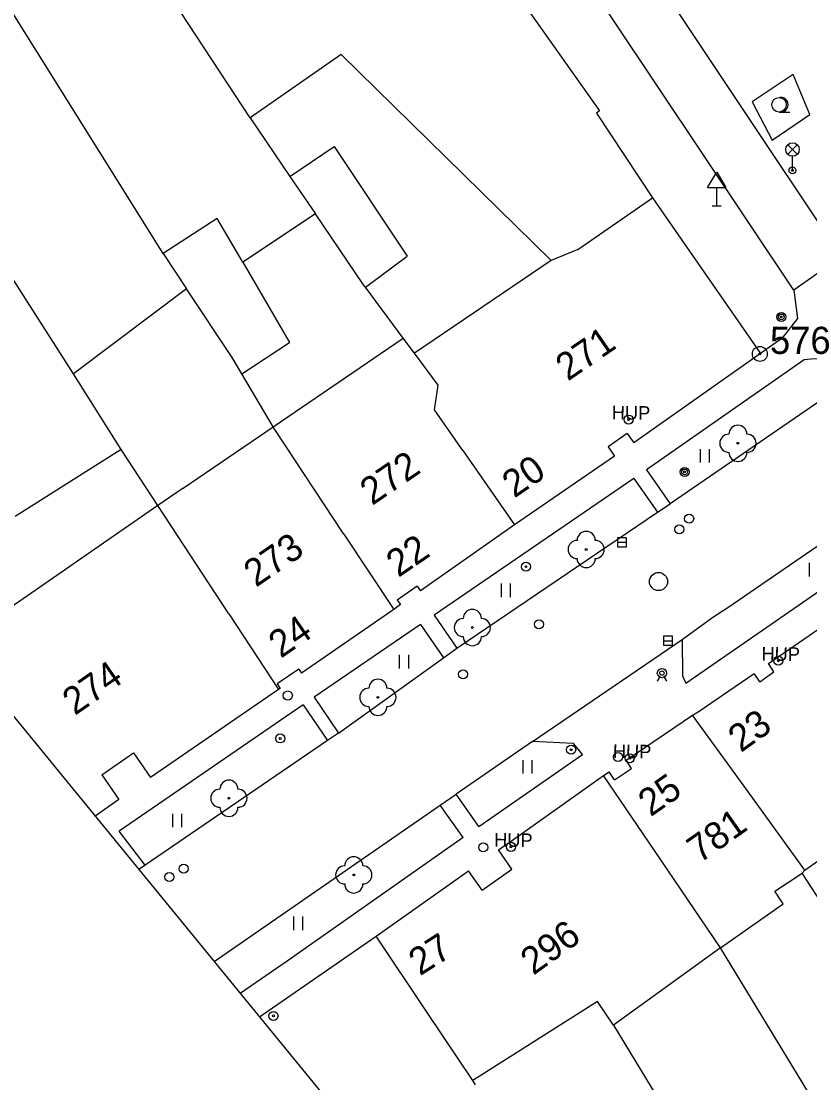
# Model space of a CAD drawing. Extents: x -492431 to -49218, y -1127123 to -112687.
# Drawn here: x -492383.5 to -492340, y -1127091 to -1127032.4 of the extents above; entities that cross this region are included whole.
import ezdxf

# ---------------------------------------------------------------- set-up
doc = ezdxf.new("R2010")
doc.units = 0
for name, color, linetype in [('Vrstva 1', 7, 'Continuous'), ('Vrstva 10', 7, 'Continuous'), ('Vrstva 11', 7, 'Continuous'), ('Vrstva 21', 7, 'Continuous'), ('Vrstva 22', 7, 'Continuous'), ('Vrstva 25', 7, 'Continuous'), ('Vrstva 27', 7, 'Continuous'), ('Vrstva 28', 7, 'Continuous'), ('Vrstva 31', 7, 'Continuous'), ('Vrstva 33', 7, 'Continuous'), ('Vrstva 34', 7, 'Continuous'), ('Vrstva 36', 7, 'Continuous'), ('Vrstva 42', 7, 'Continuous'), ('Vrstva 43', 7, 'Continuous'), ('Vrstva 44', 7, 'Continuous'), ('Vrstva 5', 7, 'Continuous'), ('Vrstva 60', 7, 'Continuous'), ('Vrstva 63', 7, 'Continuous'), ('Vrstva 7', 7, 'Continuous')]:
    doc.layers.add(name, color=color, linetype=linetype)

msp = doc.modelspace()

# ---------------------------------------------------------------- linework, layer by layer
at = {"layer": 'Vrstva 1'}
msp.add_lwpolyline([(-492431.031, -1126895.427), (-492431.031, -1127013.124), (-492341.24, -1127122.91)], dxfattribs=at)
at = {"layer": 'Vrstva 10'}
for p, q in [((-492340.27, -1127051.1), (-492348.97, -1127057.18)), ((-492337.07, -1127051.78), (-492347.66, -1127059.05)), ((-492348.97, -1127057.18), (-492347.66, -1127059.05)), ((-492349.66, -1127057.66), (-492360.68, -1127065.2)), ((-492349.66, -1127057.66), (-492348.36, -1127059.52)), ((-492346.79, -1127068.94), (-492335.59, -1127061.2)), ((-492345.31, -1127065.3), (-492344.47, -1127064.77)), ((-492361.43, -1127065.72), (-492367.3, -1127069.73)), ((-492361.43, -1127065.72), (-492360.17, -1127067.55)), ((-492360.68, -1127065.2), (-492359.43, -1127067.02)), ((-492347, -1127066.53), (-492345.31, -1127065.3)), ((-492355.26, -1127072.16), (-492347, -1127066.53)), ((-492347, -1127066.53), (-492346.97, -1127068.55)), ((-492346.97, -1127068.55), (-492346.79, -1127068.94)), ((-492367.3, -1127069.73), (-492365.95, -1127071.7)), ((-492367.91, -1127070.15), (-492378.05, -1127077.12)), ((-492367.91, -1127070.15), (-492366.56, -1127072.12)), ((-492355.26, -1127072.16), (-492359.47, -1127075.08)), ((-492352.99, -1127072.27), (-492355.26, -1127072.16)), ((-492352.49, -1127072.89), (-492352.99, -1127072.27)), ((-492358.22, -1127076.86), (-492352.49, -1127072.89)), ((-492358.22, -1127076.86), (-492359.47, -1127075.08)), ((-492359.08, -1127077.47), (-492360.34, -1127075.68)), ((-492376.61, -1127078.99), (-492378.05, -1127077.12)), ((-492359.08, -1127077.47), (-492368.79, -1127084.29)), ((-492376.61, -1127078.99), (-492376.962, -1127079.233)), ((-492368.79, -1127084.29), (-492371.373, -1127086.066))]:
    msp.add_line(p, q, dxfattribs=at)
for points in [[(-492368.22, -1127000.44), (-492338.22, -1127045.43)], [(-492340.83, -1127047.27), (-492370.84, -1127002.32)], [(-492338.22, -1127045.43), (-492340.83, -1127047.27)], [(-492340.83, -1127047.27), (-492340.63, -1127048.82), (-492341.49, -1127049.93), (-492342.67, -1127050.76)], [(-492338.96, -1127051.13), (-492339.69, -1127051.05), (-492340.27, -1127051.1)], [(-492359.43, -1127067.02), (-492348.36, -1127059.52), (-492347.66, -1127059.05)], [(-492344.47, -1127064.77), (-492336.73, -1127059.46)], [(-492365.95, -1127071.7), (-492360.17, -1127067.55), (-492359.43, -1127067.02)], [(-492365.95, -1127071.7), (-492366.56, -1127072.12), (-492376.61, -1127078.99)], [(-492360.34, -1127075.68), (-492359.47, -1127075.08)], [(-492372.806, -1127084.315), (-492360.34, -1127075.68)]]:
    msp.add_lwpolyline(points, dxfattribs=at)
at = {"layer": 'Vrstva 11'}
for points in [[(-492370.82, -1127037.75), (-492383.12, -1127019)], [(-492375.63, -1127045.24), (-492389.76, -1127022.63)], [(-492365.81, -1127034.25), (-492370.82, -1127037.75)], [(-492354.23, -1127045.63), (-492365.81, -1127034.25)], [(-492370.82, -1127037.75), (-492368.63, -1127040.99)], [(-492368.63, -1127040.99), (-492366.2, -1127039.34)], [(-492366.2, -1127039.34), (-492362.17, -1127045.38)], [(-492368.63, -1127040.99), (-492367.23, -1127043.05)], [(-492372.65, -1127043.31), (-492375.63, -1127045.24)], [(-492371.24, -1127045.71), (-492372.65, -1127043.31)], [(-492367.23, -1127043.05), (-492371.24, -1127045.71)], [(-492364.57, -1127046.97), (-492367.23, -1127043.05)], [(-492380.58, -1127051.87), (-492385.37, -1127044.39)], [(-492352.75, -1127045.01), (-492354.23, -1127045.63)], [(-492375.63, -1127045.24), (-492374.34, -1127047.18)], [(-492371.24, -1127045.71), (-492368.65, -1127050.14)], [(-492364.47, -1127047.1), (-492362.17, -1127045.38)], [(-492354.23, -1127045.63), (-492361.77, -1127050.73)], [(-492364.47, -1127047.1), (-492364.57, -1127046.97)], [(-492374.34, -1127047.18), (-492380.58, -1127051.87)], [(-492371.82, -1127050.98), (-492374.34, -1127047.18)], [(-492362.38, -1127049.91), (-492364.47, -1127047.1)], [(-492369.55, -1127054.8), (-492362.38, -1127049.91)], [(-492361.77, -1127050.73), (-492362.38, -1127049.91)], [(-492371.28, -1127051.88), (-492368.65, -1127050.14)], [(-492371.28, -1127051.88), (-492371.82, -1127050.98)], [(-492360.45, -1127052.51), (-492361.77, -1127050.73)], [(-492377.94, -1127056.05), (-492380.58, -1127051.87)], [(-492369.55, -1127054.8), (-492371.28, -1127051.88)], [(-492360.65, -1127053.87), (-492360.45, -1127052.51)], [(-492359.09, -1127056.1), (-492360.65, -1127053.87)], [(-492374.52, -1127058.18), (-492369.55, -1127054.8)], [(-492369.47, -1127054.95), (-492369.55, -1127054.8)], [(-492365.66, -1127060.72), (-492369.47, -1127054.95)], [(-492377.94, -1127056.05), (-492383.79, -1127059.75)], [(-492375.92, -1127059.15), (-492377.94, -1127056.05)], [(-492374.52, -1127058.18), (-492375.92, -1127059.15)], [(-492375.92, -1127059.15), (-492387.075, -1127066.868)], [(-492372, -1127065.12), (-492375.92, -1127059.15)], [(-492340.22, -1127079.27), (-492343.49, -1127074.77)], [(-492340.22, -1127079.27), (-492337.7, -1127077.46)], [(-492344.88, -1127083.55), (-492348.52, -1127078.19)], [(-492341.89, -1127080.42), (-492340.38, -1127079.43)], [(-492340.38, -1127079.43), (-492340.22, -1127079.27)], [(-492338.31, -1127082.6), (-492340.38, -1127079.43)], [(-492341.43, -1127081.13), (-492341.89, -1127080.42)], [(-492344.88, -1127083.55), (-492341.43, -1127081.13)], [(-492344.88, -1127083.55), (-492350.79, -1127087.82)], [(-492337.52, -1127095.66), (-492344.88, -1127083.55)], [(-492350.79, -1127087.82), (-492351.67, -1127086.51), (-492358.54, -1127090.88)], [(-492358.54, -1127090.88), (-492361.09, -1127087.07)], [(-492350.79, -1127087.82), (-492343.24, -1127100.24)], [(-492358.4, -1127091.12), (-492358.54, -1127090.88)]]:
    msp.add_lwpolyline(points, dxfattribs=at)
at = {"layer": 'Vrstva 21'}
for p, q in [((-492340.87, -1127035.36), (-492343.13, -1127036.87)), ((-492339.96, -1127037.56), (-492340.87, -1127035.36)), ((-492343.13, -1127036.87), (-492342.03, -1127038.98)), ((-492342.03, -1127038.98), (-492339.96, -1127037.56))]:
    msp.add_line(p, q, dxfattribs=at)
at = {"layer": 'Vrstva 22'}
for centre in [(-492343.92, -1127055.71), (-492352.29, -1127061.57), (-492358.57, -1127065.88), (-492363.78, -1127069.73), (-492372, -1127075.3), (-492365.11, -1127079.53)]:
    msp.add_circle(centre, 0.05, dxfattribs=at)
for centre, start, end in [((-492343.92, -1127055.21), 0, 180), ((-492344.42, -1127055.71), 90, 270), ((-492343.42, -1127055.71), 270, 90), ((-492343.92, -1127056.21), 180, 0), ((-492352.29, -1127061.07), 0, 180), ((-492352.79, -1127061.57), 90, 270), ((-492351.79, -1127061.57), 270, 90), ((-492352.29, -1127062.07), 180, 0), ((-492358.57, -1127065.38), 0, 180), ((-492359.07, -1127065.88), 90, 270), ((-492358.07, -1127065.88), 270, 90), ((-492358.57, -1127066.38), 180, 0), ((-492364.28, -1127069.73), 90, 270), ((-492363.78, -1127069.23), 0, 180), ((-492363.28, -1127069.73), 270, 90), ((-492363.78, -1127070.23), 180, 0), ((-492372, -1127074.8), 0, 180), ((-492372.5, -1127075.3), 90, 270), ((-492371.5, -1127075.3), 270, 90), ((-492372, -1127075.8), 180, 0), ((-492365.11, -1127079.03), 0, 180), ((-492365.61, -1127079.53), 90, 270), ((-492364.61, -1127079.53), 270, 90), ((-492365.11, -1127080.03), 180, 0)]:
    msp.add_arc(centre, 0.5, start, end, dxfattribs=at)
at = {"layer": 'Vrstva 25'}
for centre, radius in [((-492341.53, -1127048.74), 0.25), ((-492341.53, -1127048.74), 0.158), ((-492341.53, -1127048.74), 0.05), ((-492349.95, -1127054.4), 0.25), ((-492349.95, -1127054.4), 0.05), ((-492346.86, -1127057.29), 0.25), ((-492346.86, -1127057.29), 0.158), ((-492346.86, -1127057.29), 0.05), ((-492355.61, -1127062.52), 0.25), ((-492355.61, -1127062.52), 0.05), ((-492341.69, -1127067.71), 0.25), ((-492341.69, -1127067.71), 0.05), ((-492369.17, -1127072), 0.25), ((-492369.17, -1127072), 0.05), ((-492353.12, -1127072.62), 0.25), ((-492353.12, -1127072.62), 0.05), ((-492349.89, -1127073.09), 0.25), ((-492349.89, -1127073.09), 0.05), ((-492356.44, -1127077.98), 0.25), ((-492356.44, -1127077.98), 0.05), ((-492369.54, -1127087.31), 0.25), ((-492369.54, -1127087.31), 0.05)]:
    msp.add_circle(centre, radius, dxfattribs=at)
at = {"layer": 'Vrstva 27'}
for p, q in [((-492350.57, -1127061.17), (-492350.07, -1127061.17)), ((-492348.03, -1127066.61), (-492347.53, -1127066.61))]:
    msp.add_line(p, q, dxfattribs=at)
for points in [[(-492350.57, -1127061.42), (-492350.07, -1127061.42), (-492350.07, -1127060.92), (-492350.57, -1127060.92)], [(-492348.03, -1127066.86), (-492347.53, -1127066.86), (-492347.53, -1127066.36), (-492348.03, -1127066.36)]]:
    msp.add_lwpolyline(points, close=True, dxfattribs=at)
msp.add_circle((-492348.3, -1127063.34), 0.5, dxfattribs=at)
at = {"layer": 'Vrstva 28'}
for centre in [(-492346.61, -1127059.87), (-492347.15, -1127060.46), (-492354.89, -1127065.7), (-492359.08, -1127068.46), (-492368.75, -1127069.63), (-492350.54, -1127073.02), (-492357.97, -1127078.01), (-492374.49, -1127079.19), (-492375.29, -1127079.64)]:
    msp.add_circle(centre, 0.25, dxfattribs=at)
at = {"layer": 'Vrstva 31'}
for p, q in [((-492348.36, -1127068.841), (-492348.234, -1127068.614)), ((-492347.986, -1127068.614), (-492347.86, -1127068.841))]:
    msp.add_line(p, q, dxfattribs=at)
for radius in [0.256, 0.118]:
    msp.add_circle((-492348.11, -1127068.39), radius, dxfattribs=at)
at = {"layer": 'Vrstva 33'}
for p, q in [((-492341.175, -1127039.235), (-492340.645, -1127039.765)), ((-492341.175, -1127039.765), (-492340.645, -1127039.235)), ((-492340.91, -1127040.65), (-492340.91, -1127039.875))]:
    msp.add_line(p, q, dxfattribs=at)
for centre, radius in [((-492340.91, -1127039.5), 0.375), ((-492340.91, -1127040.65), 0.19), ((-492340.91, -1127040.65), 0.05)]:
    msp.add_circle(centre, radius, dxfattribs=at)
at = {"layer": 'Vrstva 34'}
for p, q in [((-492345.59, -1127041.6), (-492345.09, -1127040.75)), ((-492345.09, -1127040.75), (-492344.59, -1127041.6)), ((-492345.59, -1127041.6), (-492344.59, -1127041.6)), ((-492345.09, -1127042.6), (-492345.09, -1127041.6)), ((-492345.34, -1127042.6), (-492344.84, -1127042.6))]:
    msp.add_line(p, q, dxfattribs=at)
at = {"layer": 'Vrstva 36'}
for p, q in [((-492341.65, -1127037.43), (-492341.55, -1127037.43)), ((-492341.55, -1127037.43), (-492341.05, -1127037.43)), ((-492345.99, -1127056.78), (-492345.99, -1127056.03)), ((-492345.49, -1127056.78), (-492345.49, -1127056.03)), ((-492339.98, -1127063.06), (-492339.98, -1127062.31)), ((-492356.97, -1127064.2), (-492356.97, -1127063.45)), ((-492356.47, -1127064.2), (-492356.47, -1127063.45)), ((-492362.58, -1127068.13), (-492362.58, -1127067.38)), ((-492362.08, -1127068.13), (-492362.08, -1127067.38)), ((-492355.77, -1127073.94), (-492355.77, -1127073.19)), ((-492355.27, -1127073.94), (-492355.27, -1127073.19)), ((-492375.1, -1127076.9), (-492375.1, -1127076.15)), ((-492374.6, -1127076.9), (-492374.6, -1127076.15)), ((-492368.42, -1127082.57), (-492368.42, -1127081.82)), ((-492367.92, -1127082.57), (-492367.92, -1127081.82))]:
    msp.add_line(p, q, dxfattribs=at)
msp.add_circle((-492341.65, -1127037.03), 0.4, dxfattribs=at)
msp.add_arc((-492341.55, -1127037.03), 0.4, 259.69515, 97.18076, dxfattribs=at)
at = {"layer": 'Vrstva 5'}
for p, q in [((-492352.75, -1127045.01), (-492348.64, -1127042.16)), ((-492342.67, -1127050.76), (-492349.67, -1127055.68)), ((-492350.03, -1127055.17), (-492351.08, -1127055.91)), ((-492350.03, -1127055.17), (-492349.67, -1127055.68)), ((-492359.09, -1127056.1), (-492356.25, -1127060.22)), ((-492351.08, -1127055.91), (-492350.73, -1127056.42)), ((-492350.73, -1127056.42), (-492356.25, -1127060.22)), ((-492356.25, -1127060.22), (-492361.43, -1127063.86)), ((-492365.66, -1127060.72), (-492362.91, -1127064.89)), ((-492361.61, -1127063.6), (-492362.71, -1127064.37)), ((-492361.61, -1127063.6), (-492361.43, -1127063.86)), ((-492362.71, -1127064.37), (-492362.54, -1127064.61)), ((-492342.24, -1127067.87), (-492337.32, -1127064.46)), ((-492372, -1127065.12), (-492369.26, -1127069.3)), ((-492362.91, -1127064.89), (-492367.99, -1127068.4)), ((-492362.54, -1127064.61), (-492362.91, -1127064.89)), ((-492341.93, -1127068.32), (-492342.24, -1127067.87)), ((-492368.15, -1127068.17), (-492369.34, -1127068.99)), ((-492368.15, -1127068.17), (-492367.99, -1127068.4)), ((-492346.12, -1127070.53), (-492343.03, -1127068.41)), ((-492342.72, -1127068.87), (-492343.03, -1127068.41)), ((-492342.72, -1127068.87), (-492341.93, -1127068.32)), ((-492369.34, -1127068.99), (-492369.17, -1127069.24)), ((-492369.17, -1127069.24), (-492369.26, -1127069.3)), ((-492369.26, -1127069.3), (-492376.32, -1127074.16)), ((-492350.09, -1127073.2), (-492346.42, -1127070.72)), ((-492346.42, -1127070.72), (-492346.12, -1127070.53)), ((-492343.49, -1127074.77), (-492346.42, -1127070.72)), ((-492379.01, -1127074.01), (-492377.26, -1127072.8)), ((-492377.26, -1127072.8), (-492376.32, -1127074.16)), ((-492349.79, -1127073.65), (-492350.09, -1127073.2)), ((-492351.33, -1127074.05), (-492351.02, -1127073.84)), ((-492350.72, -1127074.28), (-492351.02, -1127073.84)), ((-492350.72, -1127074.28), (-492349.79, -1127073.65)), ((-492379.01, -1127074.01), (-492378.08, -1127075.36)), ((-492356.36, -1127077.61), (-492351.33, -1127074.05)), ((-492348.52, -1127078.19), (-492351.33, -1127074.05)), ((-492378.08, -1127075.36), (-492379.369, -1127076.29)), ((-492357.13, -1127078.14), (-492356.36, -1127077.61)), ((-492356.39, -1127079.22), (-492357.13, -1127078.14)), ((-492363.87, -1127082.91), (-492358.78, -1127079.3)), ((-492358.02, -1127080.37), (-492358.78, -1127079.3)), ((-492358.02, -1127080.37), (-492356.39, -1127079.22)), ((-492370.31, -1127087.367), (-492363.87, -1127082.91)), ((-492361.09, -1127087.07), (-492363.87, -1127082.91))]:
    msp.add_line(p, q, dxfattribs=at)
msp.add_lwpolyline([(-492348.64, -1127042.16), (-492342.67, -1127050.76)], dxfattribs=at)
at = {"layer": 'Vrstva 60'}
msp.add_lwpolyline([(-492431.031, -1127000), (-492431.031, -1127013.124), (-492341.24, -1127122.91), (-492166.731, -1127000)], dxfattribs=at)
at = {"layer": 'Vrstva 63'}
for radius in [0.412, 0.05]:
    msp.add_circle((-492342.71, -1127050.78), radius, dxfattribs=at)
at = {"layer": 'Vrstva 7'}
for points in [[(-492356.23, -1127030.94), (-492356.02, -1127030.79), (-492355.87, -1127031.28), (-492355, -1127032.5), (-492351.56, -1127037.37), (-492351.73, -1127037.5)], [(-492351.73, -1127037.5), (-492348.64, -1127042.16)]]:
    msp.add_lwpolyline(points, dxfattribs=at)

# ---------------------------------------------------------------- texts
at = {"layer": 'Vrstva 42'}
for p in [(-492350.88, -1127054.386), (-492342.62, -1127067.696), (-492350.82, -1127073.076), (-492357.37, -1127077.966)]:
    msp.add_text('HUP', height=0.75, rotation=359.19371, dxfattribs=at).set_placement(p)
at = {"layer": 'Vrstva 43'}
for s, rotation, p in [('271', 34.51298, (-492353.301, -1127052.311)), ('272', 34.31367, (-492364.096, -1127059.171)), ('273', 34.55286, (-492370.508, -1127063.687)), ('274', 34.75627, (-492380.501, -1127070.761)), ('781', 35.0721, (-492346.036, -1127078.92)), ('296', 35.83942, (-492355.206, -1127085.099))]:
    msp.add_text(s, height=1.5, rotation=rotation, dxfattribs=at).set_placement(p)
at = {"layer": 'Vrstva 44'}
for s, rotation, p in [('20', 34.51298, (-492356.252, -1127058.764)), ('22', 34.31367, (-492362.651, -1127063.145)), ('24', 34.55286, (-492369.135, -1127067.608)), ('23', 35.68795, (-492343.759, -1127072.81)), ('25', 35.0721, (-492348.734, -1127076.353)), ('27', 32.4453, (-492361.459, -1127085.128))]:
    msp.add_text(s, height=1.5, rotation=rotation, dxfattribs=at).set_placement(p)
at = {"layer": 'Vrstva 63'}
msp.add_text(' 576', height=1.5, dxfattribs=at).set_placement((-492342.71, -1127050.78))

doc.saveas('drawing.dxf')
